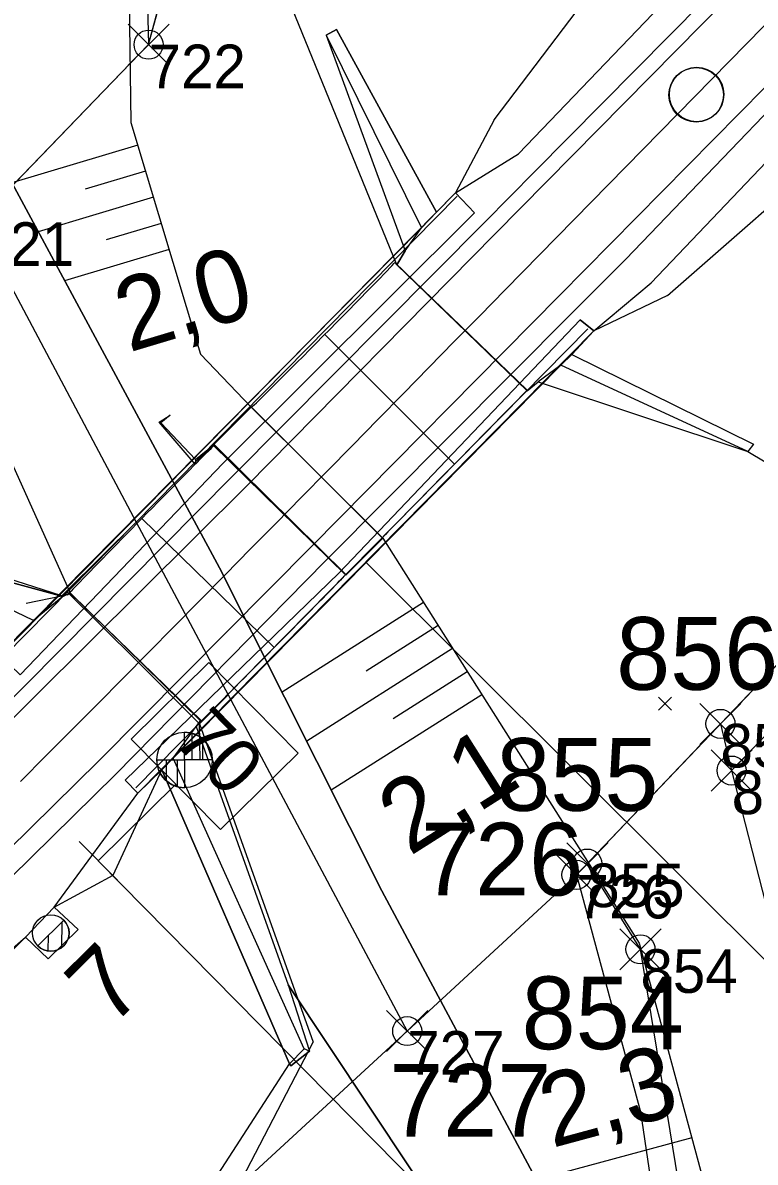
# Model space of a CAD drawing. Extents: x -800194 to -799078, y -1007177 to -1006597.
# Drawn here: x -799428.99 to -799408.83, y -1006906.14 to -1006874.78 of the extents above; entities that cross this region are included whole.
import ezdxf

# ---------------------------------------------------------------- set-up
doc = ezdxf.new("R2010")
doc.units = 0
for name, color, linetype in [('02_Osa_koleje', 7, 'Continuous'), ('_návrh', 7, 'Continuous'), ('Dočasné zábory', 7, 'Continuous'), ('Obvod stavby', 7, 'Continuous'), ('Vrstva 1', 7, 'Continuous'), ('Vrstva 11', 7, 'Continuous'), ('Vrstva 12', 7, 'Continuous'), ('Vrstva 17', 7, 'Continuous'), ('Vrstva 18', 7, 'Continuous'), ('Vrstva 4', 7, 'Continuous'), ('Vrstva 47', 7, 'Continuous'), ('Vrstva 48', 7, 'Continuous'), ('Vrstva 49', 7, 'Continuous'), ('Vrstva 5', 7, 'Continuous'), ('Vrstva 50', 7, 'Continuous'), ('Vrstva 53', 7, 'Continuous'), ('Vrstva 55', 7, 'Continuous'), ('Vrstva 56', 7, 'Continuous'), ('Vrstva 60', 7, 'Continuous'), ('Vrstva 63', 7, 'Continuous'), ('Vrstva 7', 7, 'Continuous')]:
    doc.layers.add(name, color=color, linetype=linetype)

msp = doc.modelspace()

# ---------------------------------------------------------------- linework, layer by layer
at = {"layer": '02_Osa_koleje'}
msp.add_lwpolyline([(-799415.714, -1006882.127), (-799416.414, -1006882.841), (-799417.114, -1006883.555), (-799417.815, -1006884.269), (-799418.515, -1006884.983), (-799419.215, -1006885.696), (-799419.916, -1006886.41), (-799420.617, -1006887.123), (-799421.318, -1006887.836), (-799422.019, -1006888.549), (-799422.721, -1006889.262), (-799423.423, -1006889.974), (-799424.125, -1006890.686), (-799424.828, -1006891.398), (-799425.531, -1006892.109), (-799426.234, -1006892.819), (-799426.938, -1006893.529), (-799427.643, -1006894.239), (-799428.348, -1006894.948), (-799429.054, -1006895.657)], dxfattribs=at)
at = {"layer": '_návrh'}
msp.add_line((-799415.714, -1006882.127), (-799404.558, -1006870.75), dxfattribs=at)
at = {"layer": 'Dočasné zábory'}
for p, q in [((-799410.352, -1006894.641), (-799409.221, -1006893.51)), ((-799410.352, -1006893.51), (-799409.221, -1006894.641)), ((-799410.046, -1006895.926), (-799408.914, -1006894.794)), ((-799410.046, -1006894.794), (-799408.914, -1006895.926)), ((-799414.019, -1006898.484), (-799412.887, -1006897.353)), ((-799414.019, -1006897.353), (-799412.887, -1006898.484)), ((-799412.555, -1006900.845), (-799411.423, -1006899.714)), ((-799412.555, -1006899.714), (-799411.423, -1006900.845))]:
    msp.add_line(p, q, dxfattribs=at)
for points in [[(-799409.787, -1006894.075), (-799409.48, -1006895.36), (-799407.32, -1006903.81), (-799399.52, -1006945.6), (-799393.3, -1006959.22), (-799387.62, -1006968.78), (-799386.5, -1006977.04), (-799373.965, -1006992.548), (-799373.809, -1006993.118), (-799373.66, -1006993.663), (-799374.581, -1006994.49), (-799377.093, -1006995.576), (-799395.454, -1007003.287), (-799408.652, -1007008.83)], [(-799551.8, -1007065.451), (-799550.158, -1007064.738), (-799440.86, -1007028.935), (-799429.23, -1007018.29), (-799423.8, -1007012.71), (-799421.502, -1007009.702), (-799412.394, -1007002.777), (-799410.562, -1007001.808), (-799396.882, -1006994.578), (-799395.924, -1006994.071), (-799394.941, -1006993.029), (-799394.947, -1006991.657), (-799395.98, -1006986.652), (-799406.066, -1006937.818), (-799408.053, -1006924.38), (-799411.989, -1006900.28), (-799413.453, -1006897.919)]]:
    msp.add_lwpolyline(points, dxfattribs=at)
for centre in [(-799409.787, -1006894.075), (-799409.48, -1006895.36), (-799413.453, -1006897.919), (-799411.989, -1006900.28)]:
    msp.add_circle(centre, 0.4, dxfattribs=at)
at = {"layer": 'Obvod stavby'}
for p, q in [((-799426.096, -1006875.946), (-799424.964, -1006874.814)), ((-799426.096, -1006874.814), (-799424.964, -1006875.946)), ((-799414.316, -1006898.796), (-799413.184, -1006897.664)), ((-799414.316, -1006897.664), (-799413.184, -1006898.796)), ((-799418.976, -1006903.096), (-799417.844, -1006901.964)), ((-799418.976, -1006901.964), (-799417.844, -1006903.096))]:
    msp.add_line(p, q, dxfattribs=at)
msp.add_lwpolyline([(-799559.64, -1006968.48), (-799519.68, -1006952.01), (-799500.87, -1006940.41), (-799496.64, -1006937.8), (-799494.85, -1006936.7), (-799484.52, -1006930.32), (-799457.99, -1006908.8), (-799435, -1006885.17), (-799430.26, -1006880.27), (-799425.53, -1006875.38), (-799422.55, -1006864.36), (-799416.748, -1006858.798), (-799395.763, -1006879.374), (-799413.75, -1006898.23), (-799418.41, -1006902.53), (-799423.07, -1006906.83), (-799433.4, -1006916.39), (-799469.5, -1006946.86), (-799487.22, -1006958.47), (-799495.25, -1006963.74), (-799521.98, -1006977.8), (-799546.71, -1006987.83)], dxfattribs=at)
for centre in [(-799425.53, -1006875.38), (-799413.75, -1006898.23), (-799418.41, -1006902.53)]:
    msp.add_circle(centre, 0.4, dxfattribs=at)
at = {"layer": 'Vrstva 1'}
msp.add_line((-799415.714, -1006882.127), (-799297.339, -1006761.401), dxfattribs=at)
at = {"layer": 'Vrstva 11'}
for p, q in [((-799427.864, -1006899.477), (-799428.58, -1006900.183)), ((-799427.917, -1006900.229), (-799427.913, -1006899.525)), ((-799428.293, -1006900.324), (-799428.29, -1006899.897))]:
    msp.add_line(p, q, dxfattribs=at)
msp.add_circle((-799428.222, -1006899.83), 0.503, dxfattribs=at)
msp.add_arc((-799428.222, -1006899.83), 0.503, 224.5927, 44.5927, dxfattribs=at)
at = {"layer": 'Vrstva 12'}
for p, q in [((-799425.197, -1006885.793), (-799425.235, -1006885.77)), ((-799424.241, -1006886.797), (-799424.247, -1006886.93)), ((-799427.466, -1006899.73), (-799427.466, -1006899.73)), ((-799428.298, -1006900.543), (-799428.299, -1006900.544))]:
    msp.add_line(p, q, dxfattribs=at)
for points in [[(-799423.751, -1006886.402), (-799424.247, -1006886.93), (-799425.235, -1006885.77), (-799424.934, -1006885.579)], [(-799424.934, -1006885.579), (-799425.197, -1006885.793), (-799424.241, -1006886.797), (-799423.751, -1006886.402)], [(-799428.918, -1006899.95), (-799428.299, -1006900.544), (-799427.466, -1006899.73), (-799428.131, -1006899.117)], [(-799428.918, -1006899.95), (-799428.298, -1006900.543), (-799427.466, -1006899.73), (-799428.131, -1006899.117), (-799428.918, -1006899.95)]]:
    msp.add_lwpolyline(points, dxfattribs=at)
at = {"layer": 'Vrstva 17'}
for p, q in [((-799429.476, -1006892.183), (-799417.039, -1006879.551)), ((-799413.44, -1006883.204), (-799425.878, -1006895.835))]:
    msp.add_line(p, q, dxfattribs=at)
at = {"layer": 'Vrstva 18'}
for p, q in [((-799420.643, -1006875.124), (-799418.02, -1006880.424)), ((-799418.753, -1006881.374), (-799415.11, -1006884.892)), ((-799418.695, -1006881.438), (-799415.112, -1006884.906)), ((-799413.268, -1006883.26), (-799425.823, -1006895.98)), ((-799420.678, -1006883.354), (-799417.113, -1006886.928)), ((-799422.705, -1006885.358), (-799419.086, -1006888.964)), ((-799422.697, -1006885.359), (-799419.103, -1006888.958)), ((-799423.751, -1006886.402), (-799420.096, -1006889.979)), ((-799423.712, -1006886.397), (-799420.097, -1006889.96)), ((-799425.715, -1006888.42), (-799422.073, -1006891.977)), ((-799380.318, -1006928.766), (-799419.546, -1006889.62)), ((-799427.701, -1006890.47), (-799424.076, -1006893.99)), ((-799424.101, -1006893.992), (-799427.694, -1006890.471))]:
    msp.add_line(p, q, dxfattribs=at)
for points in [[(-799420.643, -1006875.124), (-799420.353, -1006874.964), (-799417.6, -1006879.987)], [(-799420.643, -1006875.124), (-799418.471, -1006881.053), (-799418.02, -1006880.424)], [(-799429.627, -1006892.19), (-799429.629, -1006892.192), (-799429.125, -1006891.656), (-799428.698, -1006891.23), (-799418.02, -1006880.424), (-799417.6, -1006879.987), (-799417.085, -1006879.46), (-799417.085, -1006879.46)], [(-799429.07, -1006892.727), (-799423.479, -1006886.901), (-799416.56, -1006880.007), (-799417.085, -1006879.46), (-799429.627, -1006892.19), (-799429.07, -1006892.727)], [(-799416.56, -1006880.007), (-799417.085, -1006879.46)], [(-799418.753, -1006881.374), (-799418.695, -1006881.438), (-799418.471, -1006881.053)], [(-799425.824, -1006895.981), (-799425.823, -1006895.98), (-799426.173, -1006895.627), (-799425.824, -1006895.981), (-799425.17, -1006895.342), (-799424.851, -1006895.023), (-799414.182, -1006884.2), (-799413.881, -1006883.908), (-799413.271, -1006883.261), (-799413.268, -1006883.26), (-799413.647, -1006882.957), (-799413.271, -1006883.261)], [(-799426.173, -1006895.627), (-799420.283, -1006889.914), (-799413.647, -1006882.957)], [(-799413.881, -1006883.908), (-799408.874, -1006886.377), (-799409.032, -1006886.579)], [(-799414.182, -1006884.2), (-799414.808, -1006884.66), (-799409.032, -1006886.579), (-799414.182, -1006884.2)], [(-799415.11, -1006884.892), (-799415.112, -1006884.906), (-799414.808, -1006884.66)], [(-799423.712, -1006886.397), (-799423.751, -1006886.402), (-799422.705, -1006885.358), (-799422.697, -1006885.359)], [(-799420.097, -1006889.96), (-799420.096, -1006889.979), (-799419.086, -1006888.964), (-799419.103, -1006888.958)], [(-799428.698, -1006891.23), (-799432.944, -1006889.197), (-799433.133, -1006889.484)], [(-799432.944, -1006889.197), (-799427.892, -1006890.566), (-799428.698, -1006891.23)], [(-799427.892, -1006890.566), (-799427.694, -1006890.471), (-799427.701, -1006890.47)], [(-799421.25, -1006903.021), (-799424.851, -1006895.023), (-799424.223, -1006894.144), (-799421.688, -1006901.262), (-799421.096, -1006903.085)], [(-799424.223, -1006894.144), (-799424.101, -1006893.992), (-799424.076, -1006893.99)], [(-799425.17, -1006895.342), (-799421.655, -1006903.434), (-799421.617, -1006903.488), (-799421.096, -1006903.085), (-799421.25, -1006903.021), (-799421.655, -1006903.434)]]:
    msp.add_lwpolyline(points, dxfattribs=at)
for centre, major_axis, ratio, start_param, end_param in [((-799420.724, -1006883.362), (-1.983, -2.004), 0.009761, 0.092672, 3.023238), ((-799417.106, -1006886.925), (-1.997, -2.033), 0.000898, 3.15336, 6.275981), ((-799425.738, -1006888.463), (-2.026, -2.066), 0.004773, 3.137657, 6.529051), ((-799422.096, -1006891.985), (-1.999, -2.025), 0.003643, 6.144403, 9.411645)]:
    msp.add_ellipse(centre, major_axis=major_axis, ratio=ratio, start_param=start_param, end_param=end_param, dxfattribs=at)
at = {"layer": 'Vrstva 4'}
for points in [[(-799415.349, -1006878.386), (-799401.641, -1006864.104), (-799387.486, -1006849.959), (-799372.535, -1006834.618), (-799359.471, -1006821.017), (-799348.425, -1006810.321), (-799332.246, -1006792.656), (-799316.193, -1006777.023)], [(-799414.896, -1006878.87), (-799401.02, -1006864.85), (-799386.827, -1006850.567), (-799372.152, -1006835.069), (-799358.827, -1006821.464), (-799347.624, -1006811), (-799330.977, -1006793.164), (-799315.559, -1006777.544)], [(-799412.388, -1006881.287), (-799398.609, -1006866.93), (-799384.751, -1006852.862), (-799369.474, -1006837.434), (-799356.035, -1006824.081), (-799345.419, -1006813.083), (-799328.801, -1006795.774), (-799312.796, -1006779.76)], [(-799411.693, -1006881.939), (-799397.907, -1006867.466), (-799384.258, -1006853.369), (-799368.884, -1006838.066), (-799355.624, -1006824.532), (-799352.562, -1006821.889), (-799351.649, -1006821.039), (-799351.009, -1006819.785)], [(-799510.394, -1006958.536), (-799498.027, -1006951.328), (-799477.988, -1006937.435), (-799460.33, -1006923.117), (-799451.862, -1006915.581), (-799443.604, -1006907.9), (-799435.444, -1006900.067), (-799428.64, -1006893.299), (-799422.817, -1006887.511), (-799415.998, -1006880.595), (-799408.158, -1006872.652), (-799401.02, -1006864.85)], [(-799509.248, -1006960.724), (-799497.456, -1006953.809), (-799476.495, -1006939.437), (-799458.707, -1006924.982), (-799450.277, -1006917.43), (-799441.932, -1006909.717), (-799433.783, -1006901.867), (-799426.9, -1006895.092), (-799421.037, -1006889.182), (-799414.218, -1006882.281), (-799406.443, -1006874.417), (-799398.609, -1006866.93)], [(-799511.236, -1006957.129), (-799499.236, -1006950.771), (-799498.598, -1006949.914), (-799498.679, -1006949.705), (-799496.151, -1006948.479), (-799496.251, -1006948.258), (-799490.687, -1006944.683), (-799490.497, -1006944.878), (-799488.249, -1006943.052), (-799488.105, -1006943.216), (-799486.269, -1006941.68), (-799478.997, -1006936.484), (-799474.568, -1006932.916), (-799474.237, -1006932.694), (-799461.519, -1006921.99), (-799452.935, -1006914.372), (-799444.695, -1006906.886), (-799436.579, -1006898.932), (-799429.629, -1006892.192), (-799429.07, -1006892.727), (-799423.479, -1006886.901), (-799416.56, -1006880.007), (-799417.085, -1006879.46), (-799415.349, -1006878.386)], [(-799510.726, -1006958.045), (-799497.901, -1006950.516), (-799478.36, -1006937.055), (-799461.534, -1006923.53), (-799452.128, -1006915.305), (-799443.894, -1006907.632), (-799435.739, -1006899.754), (-799428.922, -1006893.007), (-799423.223, -1006887.256), (-799416.277, -1006880.269), (-799414.896, -1006878.87)], [(-799509.087, -1006961.127), (-799497.277, -1006954.118), (-799476.183, -1006939.802), (-799458.586, -1006925.284), (-799449.914, -1006917.869), (-799441.499, -1006910.139), (-799433.371, -1006902.28), (-799426.451, -1006895.478), (-799420.657, -1006889.585), (-799413.85, -1006882.742), (-799412.388, -1006881.287)], [(-799475.489, -1006940.774), (-799457.684, -1006926.366), (-799456.318, -1006925.174), (-799455.328, -1006924.513), (-799448.961, -1006918.843), (-799440.534, -1006910.864), (-799432.566, -1006903.097), (-799428.918, -1006899.95), (-799428.131, -1006899.117), (-799425.824, -1006895.981), (-799426.173, -1006895.627), (-799420.283, -1006889.914), (-799413.647, -1006882.957), (-799413.271, -1006883.261), (-799411.693, -1006881.939)]]:
    msp.add_lwpolyline(points, dxfattribs=at)
at = {"layer": 'Vrstva 47'}
msp.add_ellipse((-799432.733, -1006875.845), major_axis=(8.482, 8.158), ratio=0.02521, start_param=4.117511, end_param=5.400082, dxfattribs=at)
at = {"layer": 'Vrstva 48'}
for p, q in [((-799425.83, -1006878.145), (-799429.299, -1006879.185)), ((-799425.615, -1006878.863), (-799427.275, -1006879.361)), ((-799425.399, -1006879.581), (-799428.572, -1006880.533)), ((-799425.184, -1006880.3), (-799426.696, -1006880.753)), ((-799424.968, -1006881.018), (-799427.844, -1006881.881)), ((-799417.962, -1006890.738), (-799421.856, -1006893.206)), ((-799417.561, -1006891.372), (-799419.539, -1006892.625)), ((-799417.159, -1006892.005), (-799421.178, -1006894.552)), ((-799416.758, -1006892.639), (-799418.799, -1006893.932)), ((-799416.356, -1006893.272), (-799420.501, -1006895.898)), ((-799410.574, -1006905.468), (-799414.85, -1006906.623))]:
    msp.add_line(p, q, dxfattribs=at)
at = {"layer": 'Vrstva 49'}
for p, q in [((-799417.6, -1006879.987), (-799420.353, -1006874.964)), ((-799411.491, -1006893.34), (-799411.137, -1006893.694)), ((-799411.491, -1006893.694), (-799411.137, -1006893.34))]:
    msp.add_line(p, q, dxfattribs=at)
for points in [[(-799416.02, -1006877.454), (-799404.211, -1006861.901), (-799389.752, -1006848.65), (-799373.943, -1006833.474), (-799360.851, -1006819.663), (-799350.223, -1006808.887), (-799332.885, -1006792.133), (-799317.349, -1006776.174)], [(-799411.244, -1006882.282), (-799396.463, -1006869.344), (-799382.442, -1006854.946), (-799367.277, -1006839.246), (-799355.518, -1006825.988), (-799351.844, -1006822.661), (-799350.97, -1006821.769), (-799343.258, -1006815.248), (-799325.688, -1006798.253), (-799311.274, -1006781.732)], [(-799410.227, -1006925.149), (-799412.491, -1006911.033), (-799419.106, -1006898.668), (-799423.582, -1006889.778), (-799429.735, -1006878.378), (-799431.818, -1006855.328)], [(-799426.038, -1006858.234), (-799426.419, -1006863.568), (-799427.212, -1006869.673), (-799426.968, -1006870.003), (-799426.4, -1006870.552), (-799426.115, -1006870.824), (-799426.018, -1006877.519), (-799424.103, -1006883.903), (-799422.705, -1006885.358), (-799423.751, -1006886.402), (-799420.096, -1006889.979), (-799419.086, -1006888.964), (-799412.022, -1006900.113), (-799405.487, -1006924.286)], [(-799427.694, -1006890.471), (-799427.892, -1006890.566), (-799432.944, -1006889.197), (-799436.923, -1006881.42), (-799437.363, -1006881.152), (-799437.876, -1006880.464), (-799438.146, -1006880.193), (-799438.528, -1006878.348), (-799441.503, -1006870.303), (-799439.353, -1006865.427), (-799439.436, -1006859.851)], [(-799433.824, -1006862.471), (-799432.369, -1006880.085), (-799427.694, -1006890.471)], [(-799418.695, -1006881.438), (-799422.419, -1006872.299), (-799420.397, -1006870.813)], [(-799420.353, -1006874.964), (-799420.643, -1006875.124), (-799418.471, -1006881.053), (-799418.695, -1006881.438)], [(-799416.02, -1006877.454), (-799417.085, -1006879.46), (-799417.6, -1006879.987)], [(-799411.244, -1006882.282), (-799413.271, -1006883.261), (-799413.881, -1006883.908)], [(-799413.881, -1006883.908), (-799408.874, -1006886.377), (-799409.032, -1006886.579), (-799405.305, -1006888.801)], [(-799486.865, -1006949.018), (-799484.86, -1006947.727), (-799485.016, -1006947.459), (-799485.713, -1006947.881), (-799483.734, -1006946.536), (-799483.686, -1006946.569), (-799483.396, -1006947.063), (-799482.389, -1006946.51), (-799482.647, -1006946.068), (-799475.489, -1006940.774), (-799464.892, -1006933.871), (-799456.989, -1006927.138), (-799455.117, -1006925.642), (-799440.165, -1006911.165), (-799428.918, -1006899.95), (-799428.299, -1006900.544), (-799427.466, -1006899.73), (-799428.131, -1006899.117), (-799426.509, -1006898.237), (-799425.17, -1006895.342)], [(-799421.655, -1006903.434), (-799425.17, -1006895.342)], [(-799413.387, -1006925.296), (-799414.969, -1006911.36), (-799421.688, -1006901.262)], [(-799421.688, -1006901.262), (-799421.096, -1006903.085), (-799421.617, -1006903.488), (-799421.655, -1006903.434)], [(-799423.903, -1006906.911), (-799421.655, -1006903.434)]]:
    msp.add_lwpolyline(points, dxfattribs=at)
at = {"layer": 'Vrstva 5'}
for p, q in [((-799426.915, -1006897.844), (-799424.779, -1006895.738)), ((-799427.442, -1006897.31), (-799426.388, -1006898.378)), ((-799389.844, -1006935.446), (-799426.915, -1006897.844))]:
    msp.add_line(p, q, dxfattribs=at)
msp.add_lwpolyline([(-799423.55, -1006896.984), (-799426.007, -1006894.492), (-799423.871, -1006892.385), (-799421.414, -1006894.878)], close=True, dxfattribs=at)
at = {"layer": 'Vrstva 50'}
for points in [[(-799431.818, -1006855.328), (-799429.735, -1006878.378), (-799423.582, -1006889.778), (-799419.106, -1006898.668), (-799412.491, -1006911.033), (-799410.227, -1006925.149)], [(-799433.824, -1006862.471), (-799432.369, -1006880.085), (-799427.694, -1006890.471), (-799424.101, -1006893.992), (-799424.223, -1006894.144), (-799421.688, -1006901.262), (-799414.969, -1006911.36), (-799413.387, -1006925.296)]]:
    msp.add_lwpolyline(points, dxfattribs=at)
at = {"layer": 'Vrstva 53'}
for points in [[(-799559.64, -1006968.48), (-799519.68, -1006952.01), (-799500.87, -1006940.41), (-799496.64, -1006937.8), (-799494.85, -1006936.7), (-799484.519, -1006930.319), (-799457.99, -1006908.8), (-799435, -1006885.17), (-799430.26, -1006880.27), (-799425.53, -1006875.38), (-799422.55, -1006864.36), (-799390.88, -1006834), (-799358.35, -1006806.65), (-799352.29, -1006801.56), (-799330.91, -1006783.58), (-799314.235, -1006766.649)], [(-799312.398, -1006791.976), (-799331.37, -1006811.87), (-799413.75, -1006898.23), (-799418.41, -1006902.53), (-799423.07, -1006906.83), (-799433.4, -1006916.39), (-799469.5, -1006946.86), (-799487.22, -1006958.47), (-799495.25, -1006963.74), (-799521.98, -1006977.8), (-799546.71, -1006987.83)]]:
    msp.add_lwpolyline(points, dxfattribs=at)
at = {"layer": 'Vrstva 55'}
for p, q in [((-799413.75, -1006898.23), (-799331.37, -1006811.87)), ((-799425.53, -1006875.38), (-799422.55, -1006864.36)), ((-799425.53, -1006875.38), (-799430.26, -1006880.27)), ((-799430.26, -1006880.27), (-799425.87, -1006888.52)), ((-799425.87, -1006888.52), (-799423.34, -1006893.28)), ((-799423.34, -1006893.28), (-799418.41, -1006902.53)), ((-799418.41, -1006902.53), (-799413.75, -1006898.23)), ((-799423.07, -1006906.83), (-799418.41, -1006902.53))]:
    msp.add_line(p, q, dxfattribs=at)
for points in [[(-799422.547, -1006766.649), (-799420.88, -1006776.85), (-799422, -1006788.79), (-799422.77, -1006803.25), (-799426.4, -1006820.84), (-799428.26, -1006838.83), (-799427.88, -1006846.03), (-799426.08, -1006854.14), (-799425.53, -1006875.38)], [(-799329.14, -1006812.3), (-799409.48, -1006895.36), (-799407.32, -1006903.81)], [(-799413.75, -1006898.23), (-799411.99, -1006904.75), (-799406.72, -1006940.36), (-799397.01, -1006988.73)]]:
    msp.add_lwpolyline(points, dxfattribs=at)
at = {"layer": 'Vrstva 56'}
for p, q in [((-799427.92, -1006890.55), (-799434.41, -1006888.48)), ((-799427.79, -1006890.42), (-799425.87, -1006888.52)), ((-799428.899, -1006890.757), (-799427.921, -1006890.55)), ((-799427.92, -1006890.55), (-799427.79, -1006890.42)), ((-799427.79, -1006890.42), (-799425.84, -1006892.36)), ((-799425.84, -1006892.36), (-799424.13, -1006894.07)), ((-799423.34, -1006893.28), (-799424.13, -1006894.07)), ((-799424.113, -1006895.07), (-799424.131, -1006894.071)), ((-799424.13, -1006894.07), (-799421, -1006902.84)), ((-799423.07, -1006906.83), (-799421, -1006902.84))]:
    msp.add_line(p, q, dxfattribs=at)
at = {"layer": 'Vrstva 60'}
for p, q in [((-799425.53, -1006875.38), (-799425.53, -1006875.38)), ((-799409.787, -1006894.075), (-799409.787, -1006894.075)), ((-799409.48, -1006895.36), (-799409.48, -1006895.36)), ((-799413.453, -1006897.919), (-799413.453, -1006897.919)), ((-799413.75, -1006898.23), (-799413.75, -1006898.23)), ((-799411.989, -1006900.279), (-799411.989, -1006900.279)), ((-799418.41, -1006902.53), (-799418.41, -1006902.53))]:
    msp.add_line(p, q, dxfattribs=at)
at = {"layer": 'Vrstva 63'}
for p, q in [((-799424.541, -1006895.067), (-799424.542, -1006894.303)), ((-799424.333, -1006895.067), (-799424.334, -1006894.331)), ((-799424.033, -1006895.067), (-799424.033, -1006894.496)), ((-799425.305, -1006895.062), (-799424.541, -1006895.067)), ((-799425.037, -1006895.649), (-799425.037, -1006895.064)), ((-799424.737, -1006895.806), (-799424.737, -1006895.066)), ((-799423.776, -1006895.066), (-799424.541, -1006895.067)), ((-799424.541, -1006895.067), (-799424.54, -1006895.832))]:
    msp.add_line(p, q, dxfattribs=at)
msp.add_circle((-799424.541, -1006895.067), 0.764, dxfattribs=at)
for centre, start, end in [((-799424.542, -1006895.068), 0.1128, 90.0063), ((-799424.54, -1006895.066), 179.662, 269.98)]:
    msp.add_arc(centre, 0.765, start, end, dxfattribs=at)
at = {"layer": 'Vrstva 7'}
for centre in [(-799410.454, -1006876.763), (-799410.443, -1006876.752)]:
    msp.add_circle(centre, 0.75, dxfattribs=at)

# ---------------------------------------------------------------- texts
at = {"layer": 'Dočasné zábory'}
for s, p in [('856', (-799412.658, -1006893.137)), ('855', (-799415.956, -1006896.467)), ('854', (-799415.261, -1006903.029))]:
    msp.add_text(s, height=2, rotation=360, dxfattribs=at).set_placement(p)
at = {"layer": 'Obvod stavby'}
for s, p in [('726', (-799418.028, -1006898.798)), ('727', (-799418.906, -1006905.438))]:
    msp.add_text(s, height=2, rotation=360, dxfattribs=at).set_placement(p)
at = {"layer": 'Vrstva 11'}
msp.add_text('7', height=2, rotation=44.5927, dxfattribs=at).set_placement((-799426.568, -1006902.454))
at = {"layer": 'Vrstva 48'}
for s, rotation, p in [('2,0', 16.6976, (-799426.075, -1006883.857)), ('2,1', 32.3583, (-799418.346, -1006897.73)), ('2,3', 15.1279, (-799414.428, -1006905.752))]:
    msp.add_text(s, height=2, rotation=rotation, dxfattribs=at).set_placement(p)
at = {"layer": 'Vrstva 5'}
msp.add_text('70', height=1.5, rotation=314.5927, dxfattribs=at).set_placement((-799424.886, -1006894.561))
at = {"layer": 'Vrstva 60'}
for s, p in [('722', (-799425.53, -1006876.58)), ('721', (-799430.26, -1006881.47)), ('856', (-799409.787, -1006895.275)), ('857', (-799409.48, -1006896.56)), ('855', (-799413.453, -1006899.119)), ('726', (-799413.75, -1006899.43)), ('854', (-799411.989, -1006901.479)), ('727', (-799418.41, -1006903.73))]:
    msp.add_text(s, height=1.2, dxfattribs=at).set_placement(p)

doc.saveas('drawing.dxf')
